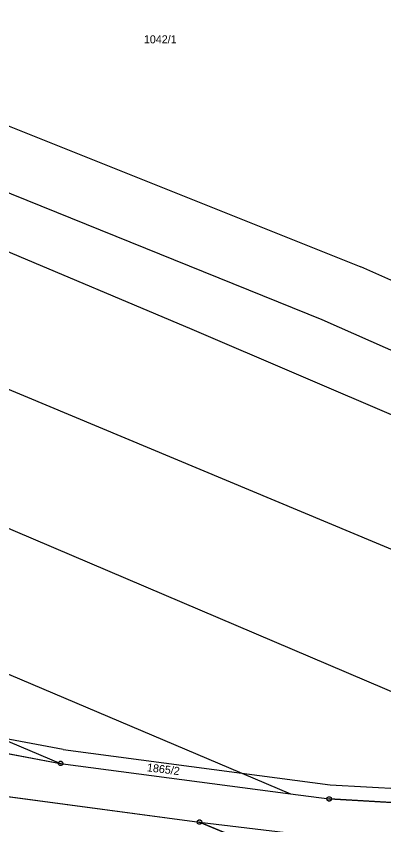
# Model space of a CAD drawing. Extents: x -777309 to -774195, y -1144706 to -1143600.
# Drawn here: x -775484.3 to -775406.4, y -1144462.3 to -1144290.6 of the extents above; entities that cross this region are included whole.
import ezdxf

# ---------------------------------------------------------------- set-up
doc = ezdxf.new("R2010")
doc.units = 0
for name, color, linetype in [('1', 7, 'Continuous'), ('11', 7, 'Continuous'), ('2', 7, 'Continuous'), ('8', 7, 'Continuous')]:
    doc.layers.add(name, color=color, linetype=linetype)

msp = doc.modelspace()

# ---------------------------------------------------------------- linework, layer by layer
at = {"layer": '1'}
for p, q in [((-775618.95, -1144284.54), (-775447.05, -1144357.1)), ((-775543.76, -1144290.79), (-775411.19, -1144343.87)), ((-775394.06, -1144408.34), (-775619.55, -1144313.89)), ((-775419.42, -1144355.11), (-775522.49, -1144313.33)), ((-775388.13, -1144354.18), (-775411.19, -1144343.87)), ((-775391.09, -1144367.64), (-775419.42, -1144355.11)), ((-775447.05, -1144357.1), (-775391.08, -1144381.09)), ((-775397.11, -1144437.29), (-775575.13, -1144361.42)), ((-775595.92, -1144383.54), (-775436.47, -1144451.33)), ((-775529.11, -1144439.07), (-775474.88, -1144449.28)), ((-775487.96, -1144443.76), (-775474.88, -1144449.28)), ((-775474.32, -1144446.33), (-775487.96, -1144443.76)), ((-775474.32, -1144446.33), (-775436.47, -1144451.33)), ((-775474.88, -1144449.28), (-775426.17, -1144455.72)), ((-775436.47, -1144451.33), (-775426.17, -1144455.72)), ((-775436.47, -1144451.33), (-775417.75, -1144453.81)), ((-775417.75, -1144453.81), (-775384.8, -1144455.7)), ((-775493.48, -1144455.3), (-775445.43, -1144461.73)), ((-775426.17, -1144455.72), (-775417.93, -1144456.81)), ((-775377.95, -1144459.1), (-775417.93, -1144456.81)), ((-775435.74, -1144465.74), (-775445.43, -1144461.73)), ((-775445.43, -1144461.73), (-775425.39, -1144464.15))]:
    msp.add_line(p, q, dxfattribs=at)
at = {"layer": '11'}
for points in [[(-775666.42, -1144398.43), (-775626.91, -1144413.11), (-775574.03, -1144428.55), (-775529.11, -1144439.07), (-775474.88, -1144449.28), (-775426.17, -1144455.72), (-775417.93, -1144456.81), (-775377.95, -1144459.1), (-775351.35, -1144460.68), (-775341.64, -1144460.83), (-775337.71, -1144460.89), (-775301.48, -1144461.27), (-775254.16, -1144459.9), (-775170.99, -1144453.66), (-775164.13, -1144452.88)], [(-775493.48, -1144455.3), (-775445.43, -1144461.73), (-775435.74, -1144465.74), (-775366.41, -1144494.44), (-775328.85, -1144510.01), (-775310.26, -1144517.79), (-775294.22, -1144525.5), (-775270.96, -1144536.68), (-775261.18, -1144541.39), (-775253.51, -1144525.7), (-775380, -1144472.53), (-775389.68, -1144468.46), (-775332.79, -1144469.99), (-775289.7, -1144468.96), (-775237.91, -1144466.56), (-775217.76, -1144465.11), (-775204.62, -1144464.16), (-775201.24, -1144463.92), (-775148.23, -1144459.85)]]:
    msp.add_lwpolyline(points, dxfattribs=at)
at = {"layer": '8'}
for p, q in [((-775475, -1144449.28), (-775474.76, -1144449.28)), ((-775418.05, -1144456.81), (-775417.81, -1144456.81)), ((-775445.55, -1144461.73), (-775445.31, -1144461.73))]:
    msp.add_line(p, q, dxfattribs=at)
for points in [[(-775474.73, -1144448.8), (-775474.48, -1144448.98), (-775474.38, -1144449.27), (-775474.48, -1144449.56), (-775474.73, -1144449.74), (-775475.04, -1144449.74), (-775475.29, -1144449.56), (-775475.39, -1144449.27), (-775475.29, -1144448.98), (-775475.04, -1144448.8)], [(-775417.78, -1144456.33), (-775417.53, -1144456.51), (-775417.43, -1144456.8), (-775417.53, -1144457.09), (-775417.78, -1144457.27), (-775418.09, -1144457.27), (-775418.34, -1144457.09), (-775418.44, -1144456.8), (-775418.34, -1144456.51), (-775418.09, -1144456.33)], [(-775445.28, -1144461.25), (-775445.03, -1144461.43), (-775444.93, -1144461.72), (-775445.03, -1144462.01), (-775445.28, -1144462.19), (-775445.59, -1144462.19), (-775445.84, -1144462.01), (-775445.94, -1144461.72), (-775445.84, -1144461.43), (-775445.59, -1144461.25)]]:
    msp.add_lwpolyline(points, close=True, dxfattribs=at)

# ---------------------------------------------------------------- texts
at = {"layer": '2'}
msp.add_text('1042/1', height=1.7, dxfattribs=at).set_placement((-775457.23, -1144296.39))
msp.add_text('1865/2', height=1.7, rotation=352.9993, dxfattribs=at).set_placement((-775456.64, -1144450.92))

doc.saveas('drawing.dxf')
